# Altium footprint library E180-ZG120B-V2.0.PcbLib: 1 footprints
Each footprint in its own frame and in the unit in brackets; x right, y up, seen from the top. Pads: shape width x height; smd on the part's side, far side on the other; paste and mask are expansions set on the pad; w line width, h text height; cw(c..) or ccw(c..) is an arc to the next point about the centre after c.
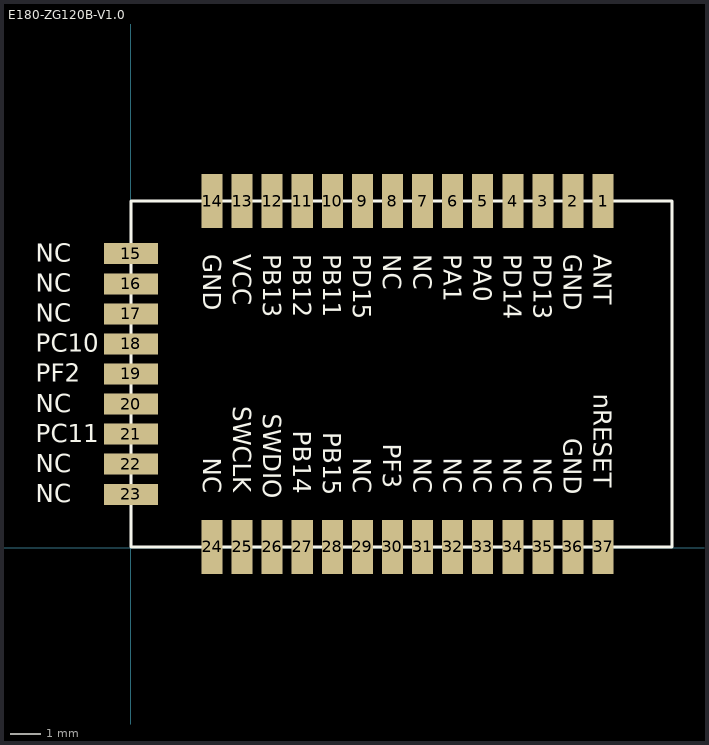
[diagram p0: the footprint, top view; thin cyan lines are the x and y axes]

## E180-ZG120B-V1.0 [mm]
pads (37):
  rect 0.7x1.8 smd: 1(15.7,11.528) 2(14.7,11.528) 3(13.7,11.528) 4(12.7,11.528) 5(11.7,11.528) 6(10.7,11.528) 7(9.7,11.528) 8(8.7,11.528) 9(7.7,11.528) 10(6.7,11.528) 11(5.7,11.528) 12(4.7,11.528) 13(3.7,11.528) 14(2.7,11.528) 24(2.7,0.028) 25(3.7,0.028) 26(4.7,0.028) 27(5.7,0.028) 28(6.7,0.028) 29(7.7,0.028) 30(8.7,0.028) 31(9.7,0.028) 32(10.7,0.028) 33(11.7,0.028) 34(12.7,0.028) 35(13.7,0.028) 36(14.7,0.028) 37(15.7,0.028)
  rect 1.8x0.7 smd: 15(0,9.778) 16(0,8.778) 17(0,7.778) 18(0,6.778) 19(0,5.778) 20(0,4.778) 21(0,3.778) 22(0,2.778) 23(0,1.778)
Top Overlay:
  lines w0.1: 0,0.028 18,0.028 18,11.528 0,11.528 0,0.028
  text "PC10" at -3.16,6.512 h0.6
  text "NC" at -3.16,8.512 h0.6
  text "NC" at -3.16,2.512 h0.6
  text "NC" at -3.16,4.512 h0.6
  text "NC" at -3.16,9.512 h0.6
  text "NC" at -3.16,7.512 h0.6
  text "PF2" at -3.16,5.512 h0.6
  text "PC11" at -3.16,3.512 h0.6
  text "NC" at -3.16,1.512 h0.6
  text "nRESET" at 15.4,5.124 h0.6
  text "NC" at 11.4,2.991 h0.6
  text "NC" at 13.4,2.991 h0.6
  text "SWCLK" at 3.4,4.699 h0.6
  text "NC" at 9.4,2.991 h0.6
  text "NC" at 7.4,2.991 h0.6
  text "PB14" at 5.4,3.893 h0.6
  text "NC" at 12.4,2.991 h0.6
  text "SWDIO" at 4.4,4.459 h0.6
  text "GND" at 14.4,3.639 h0.6
  text "NC" at 10.4,2.991 h0.6
  text "PF3" at 8.4,3.45 h0.6
  text "PB15" at 6.4,3.836 h0.6
  text "NC" at 2.4,2.991 h0.6
  text "PD13" at 13.4,9.759 h0.6
  text "PB12" at 5.4,9.759 h0.6
  text "ANT" at 15.4,9.759 h0.6
  text "NC" at 9.4,9.759 h0.6
  text "PA0" at 11.4,9.759 h0.6
  text "PD15" at 7.4,9.759 h0.6
  text "VCC" at 3.4,9.759 h0.6
  text "PD14" at 12.4,9.759 h0.6
  text "PB11" at 6.4,9.759 h0.6
  text "PB13" at 4.4,9.759 h0.6
  text "GND" at 14.4,9.759 h0.6
  text "PA1" at 10.4,9.759 h0.6
  text "NC" at 8.4,9.759 h0.6
  text "GND" at 2.4,9.759 h0.6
